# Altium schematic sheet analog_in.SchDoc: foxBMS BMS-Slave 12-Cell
size A3; DocumentNumber: 7; SheetNumber: 7; SheetTotal: 15; AUTHOR: Fraunhofer IISB foxBMS Team; SheetDescription: Primary Analog Inputs
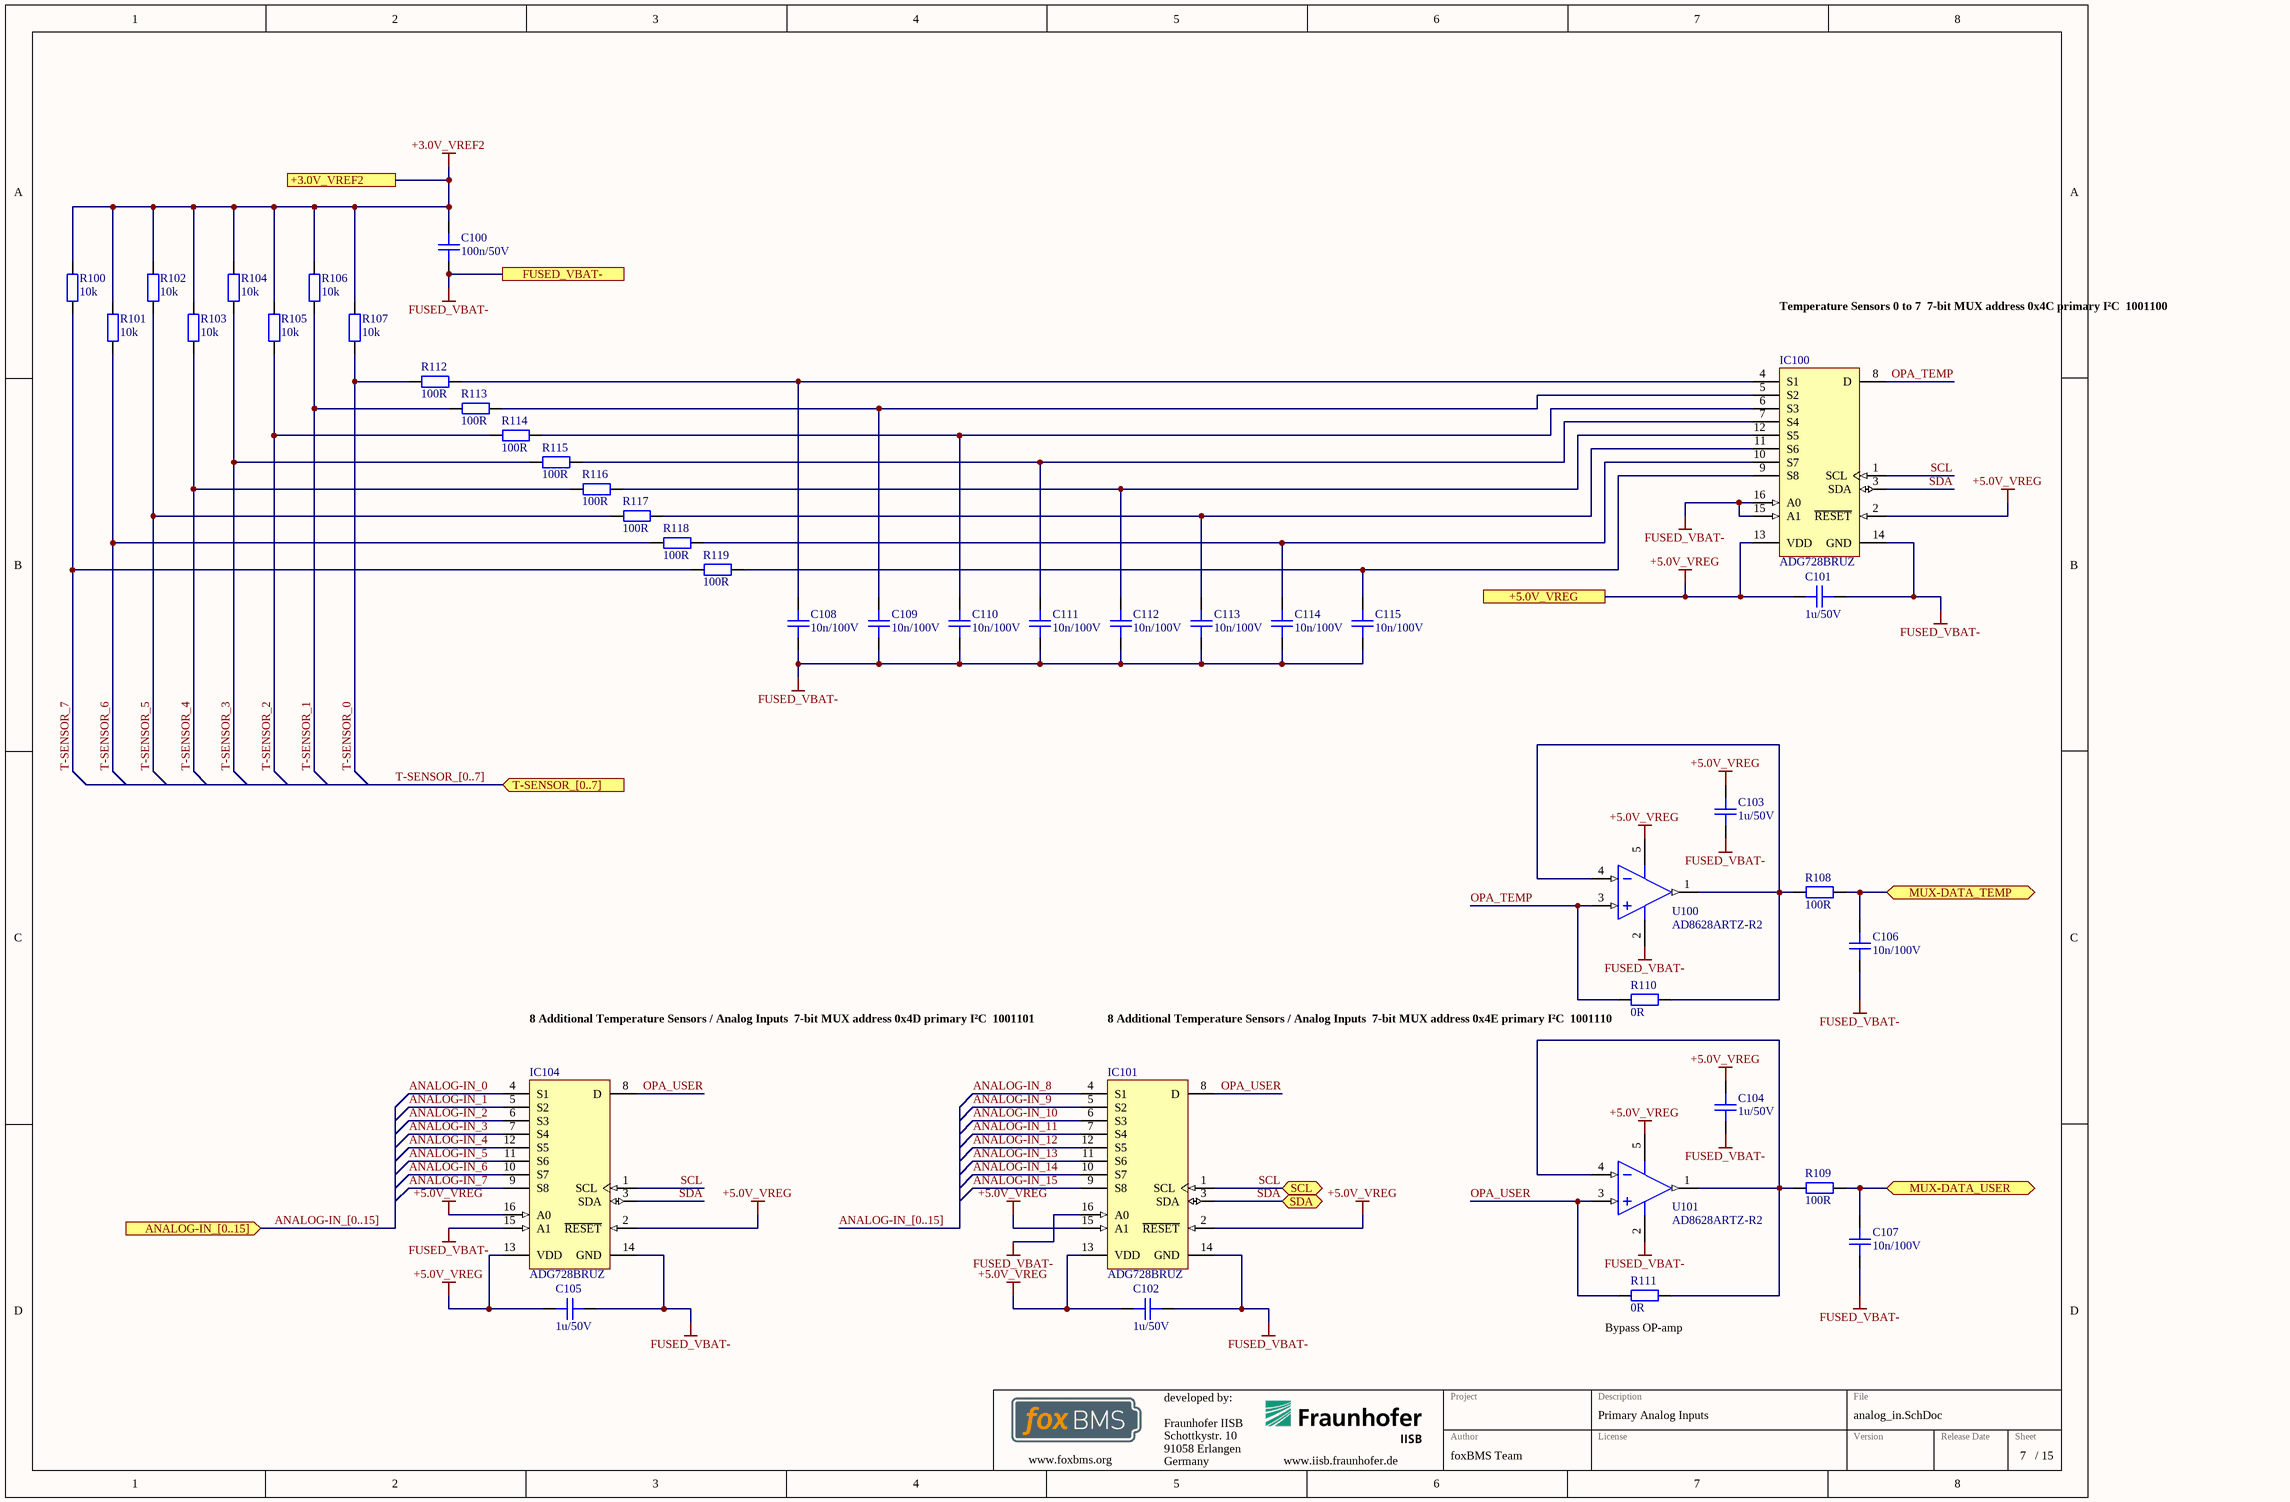
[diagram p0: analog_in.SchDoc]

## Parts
C100  100n/50V  [CAPC1608X08N]
C101  1u/50V  [CAPC2012X14N]
C102  1u/50V  [CAPC2012X14N]
C103  1u/50V  [CAPC2012X14N]
C104  1u/50V  [CAPC2012X14N]
C105  1u/50V  [CAPC2012X14N]
C106  10n/100V  [CAPC1608X08N]
C107  10n/100V  [CAPC1608X08N]
C108  10n/100V  [CAPC1608X08N]
C109  10n/100V  [CAPC1608X08N]
C110  10n/100V  [CAPC1608X08N]
C111  10n/100V  [CAPC1608X08N]
C112  10n/100V  [CAPC1608X08N]
C113  10n/100V  [CAPC1608X08N]
C114  10n/100V  [CAPC1608X08N]
C115  10n/100V  [CAPC1608X08N]
IC100  ADG728BRUZ  [ADI-RU-16_M]
IC101  ADG728BRUZ  [ADI-RU-16_M]
IC104  ADG728BRUZ  [ADI-RU-16_M]
R100  10k  [RESC1608X05N]
R101  10k  [RESC1608X05N]
R102  10k  [RESC1608X05N]
R103  10k  [RESC1608X05N]
R104  10k  [RESC1608X05N]
R105  10k  [RESC1608X05N]
R106  10k  [RESC1608X05N]
R107  10k  [RESC1608X05N]
R108  100R  [RESC1608X05N]
R109  100R  [RESC1608X05N]
R110  0R  [RESC1608X05N]
R111  0R  [RESC1608X05N]
R112  100R  [RESC1608X05N]
R113  100R  [RESC1608X05N]
R114  100R  [RESC1608X05N]
R115  100R  [RESC1608X05N]
R116  100R  [RESC1608X05N]
R117  100R  [RESC1608X05N]
R118  100R  [RESC1608X05N]
R119  100R  [RESC1608X05N]
U100  AD8628ARTZ-R2  [ADI-RJ-5_M]
U101  AD8628ARTZ-R2  [ADI-RJ-5_M]

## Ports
+3.0V_VREF2, +5.0V_VREG, ANALOG-IN_[0..15] (in), FUSED_VBAT-, MUX-DATA_TEMP (bidir), MUX-DATA_USER (bidir), SCL (bidir), SDA (bidir), T-SENSOR_[0..7] (in)

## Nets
+3.0V_VREF2: C100.2 R100.2 R101.2 R102.2 R103.2 R104.2 R105.2 R106.2 R107.2 ; port +3.0V_VREF2
+5.0V_VREG: C101.2 C102.2 C103.2 C104.2 C105.2 IC100.2(~{RESET}) IC100.13(VDD) IC101.2(~{RESET}) IC101.13(VDD) IC101.15(A1) IC104.2(~{RESET}) IC104.13(VDD) IC104.16(A0) U100.5(+V) U101.5(+V) ; port +5.0V_VREG
FUSED_VBAT-: C100.1 C101.1 C102.1 C103.1 C104.1 C105.1 C106.1 C107.1 C108.1 C109.1 C110.1 C111.1 C112.1 C113.1 C114.1 C115.1 IC100.14(GND) IC100.15(A1) IC100.16(A0) IC101.14(GND) IC101.16(A0) IC104.14(GND) IC104.15(A1) U100.2(-V) U101.2(-V) ; port FUSED_VBAT-
ANALOG-IN_0: IC104.4(S1)
ANALOG-IN_1: IC104.5(S2)
ANALOG-IN_2: IC104.6(S3)
ANALOG-IN_3: IC104.7(S4)
ANALOG-IN_4: IC104.12(S5)
ANALOG-IN_5: IC104.11(S6)
ANALOG-IN_6: IC104.10(S7)
ANALOG-IN_7: IC104.9(S8)
ANALOG-IN_8: IC101.4(S1)
ANALOG-IN_9: IC101.5(S2)
ANALOG-IN_10: IC101.6(S3)
ANALOG-IN_11: IC101.7(S4)
ANALOG-IN_12: IC101.12(S5)
ANALOG-IN_13: IC101.11(S6)
ANALOG-IN_14: IC101.10(S7)
ANALOG-IN_15: IC101.9(S8)
MUX-DATA_TEMP: C106.2 R108.2 ; port MUX-DATA_TEMP
MUX-DATA_USER: C107.2 R109.2 ; port MUX-DATA_USER
OPA_TEMP: IC100.8(D) R110.1 U100.3(+IN)
OPA_USER: IC101.8(D) IC104.8(D) R111.1 U101.3(+IN)
SCL: IC100.1(SCL) IC101.1(SCL) IC104.1(SCL) ; port SCL
SDA: IC100.3(SDA) IC101.3(SDA) IC104.3(SDA) ; port SDA
T-SENSOR_0: R107.1 R112.2
T-SENSOR_1: R106.1 R113.2
T-SENSOR_2: R105.1 R114.2
T-SENSOR_3: R104.1 R115.2
T-SENSOR_4: R103.1 R116.2
T-SENSOR_5: R102.1 R117.2
T-SENSOR_6: R101.1 R118.2
T-SENSOR_7: R100.1 R119.2
NetC108_2: C108.2 IC100.4(S1) R112.1
NetC109_2: C109.2 IC100.5(S2) R113.1
NetC110_2: C110.2 IC100.6(S3) R114.1
NetC111_2: C111.2 IC100.7(S4) R115.1
NetC112_2: C112.2 IC100.12(S5) R116.1
NetC113_2: C113.2 IC100.11(S6) R117.1
NetC114_2: C114.2 IC100.10(S7) R118.1
NetC115_2: C115.2 IC100.9(S8) R119.1
NetR108_1: R108.1 R110.2 U100.1(OUT) U100.4(-IN)
NetR109_1: R109.1 R111.2 U101.1(OUT) U101.4(-IN)

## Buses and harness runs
bus ANALOG-IN_[0..15]
bus ANALOG-IN_[0..15] = port ANALOG-IN_[0..15]
bus T-SENSOR_[0..7] = port T-SENSOR_[0..7]

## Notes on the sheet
- Temperature Sensors 0 to 7
  7-bit MUX address 0x4C primary I²C
  1001100
- 8 Additional Temperature Sensors / Analog Inputs
  7-bit MUX address 0x4D primary I²C
  1001101
- (near R110) 8 Additional Temperature Sensors / Analog Inputs
  7-bit MUX address 0x4E primary I²C
  1001110
- (near R111) Bypass OP-amp

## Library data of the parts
C100 = gen_C_ceramic_100n_50V_X7R_0603: MLCC; Capacitance: 100n; Rated Voltage: 50V; Dielectric: X7R; Case EIA: 0603; Case Metric: 1608; PnP Package: C_0603_10; PnP Value: 100n/50V/X7R; PnP equipped: x; Automotive Qualified: True
C101-C105 = gen_C_ceramic_1u_50V_X7R_0805: MLCC; Capacitance: 1u; Rated Voltage: 50V; Dielectric: X7R; Case EIA: 0805; Case Metric: 2012; Automotive Qualified: True; Tolerance: ± 10%; AVT Set: x
C106-C115 = gen_C_ceramic_10n_100V_X7R_0603: MLCC; Capacitance: 10n; Rated Voltage: 100V; Dielectric: X7R; Case EIA: 0603; Case Metric: 1608; Automotive Qualified: True
IC100 IC101 IC104 = CMP-0798-00197-1: CMOS, Low Voltage, 2-Wire Serially Controlled, Matrix Switch, -40 to 85 degC, 16-pin SOP (RU-16), Tube; Manufacturer: Analog Devices; Ron (ohms): 2.5; Supply V Guar Performance: Single_(+3V), Single_(+5V); Max Analog Signal Range: 0 to Vdd; Bandwidth (Hz): 65M
R100-R107 = gen_R_10k_0603: SMD Resistor 10k 0603; Tolerance: 1%; Power: 0.1W; Case EIA: 0603; Case Metric: 1608; Maximum Working Voltage: 75V; PnP Package: R_0603; Automotive Qualified: True
R108 R109 R112-R119 = gen_R_100R_0603: SMD Resistor 100R 0603; Tolerance: 1%; Power: 0.1W; Case EIA: 0603; Case Metric: 1608; Maximum Working Voltage: 75V; PnP Package: R_0603; Automotive Qualified: True
R110 R111 = gen_R_0R_0603: SMD Resistor 0R 0603; Power: 0.1W; Case EIA: 0603; Case Metric: 1608; Maximum Working Voltage: 75V; PnP Package: R_0603; Automotive Qualified: True
U100 U101 = CMP-0384-01512-2: Single Channel RRIO Operational Amplifier, 2.5 MHz BW, 1 V/us SR, Industrial, 5-pin SOT23 (RJ-5), Reel; Manufacturer: Analog Devices; Generic Part Number: AD8628; Iq/Amp: 1.1mA; Automotive Qualified: Yes; V Span Max: 6V; Input Bias Current: 30pA; Slew Rate: 1V/us; Amplifiers Per Package: 1; Input Offset Voltage: 1uV; Small Signal Bandwidth: 2.5MHz; V Span Min: 2.7V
